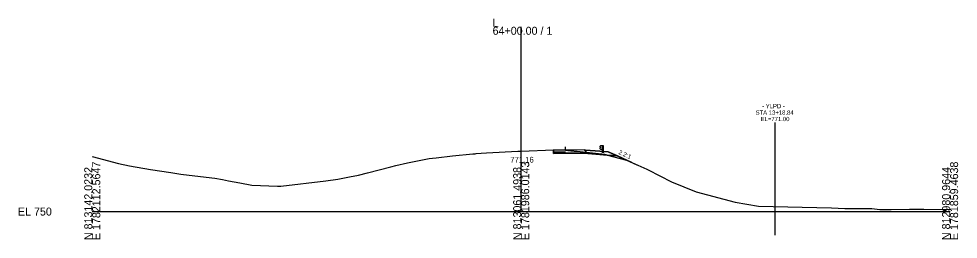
# Model space of a CAD drawing. Extents: x -26 to 7903, y -10 to 9573.
# Drawn here: x 2974.3 to 3302.8, y 4990.3 to 5067.5 of the extents above; entities that cross this region are included whole.
import ezdxf

# ---------------------------------------------------------------- set-up
doc = ezdxf.new("R2010")
doc.units = 0
for name, color, linetype in [('Exist Cross Section Cell', 7, 'Continuous'), ('Exist XS Center Line Elevation Label', 7, 'Continuous'), ('Exist XS Ground Line', 7, 'Continuous'), ('Prop XS Dump Level', 7, 'Continuous'), ('Prop XS Earthwork Shape', 7, 'Continuous'), ('Prop XS EOT Tick Mark', 7, 'Continuous'), ('Prop XS Finish Grade', 7, 'Continuous'), ('Prop XS Finish Grade Earthwork', 7, 'Continuous'), ('Prop XS Finish Grade Paved Shoulder', 7, 'Continuous'), ('Prop XS Finish Grade Pavement', 7, 'Continuous'), ('Prop XS Guardrail', 7, 'Continuous'), ('Prop XS Hydro Fill Slope Data', 7, 'Continuous'), ('Prop XS Pvmt Edge Slope', 7, 'Continuous'), ('Prop XS Side Slope Text', 7, 'Continuous'), ('Prop XS Subgrade Earthwork', 7, 'Continuous'), ('Prop XS Vertical Lines Alignments', 7, 'Continuous'), ('Scratch_Level_3', 7, 'Continuous'), ('Scratch_Level_6', 7, 'Continuous')]:
    doc.layers.add(name, color=color, linetype=linetype)

msp = doc.modelspace()

# ---------------------------------------------------------------- linework, layer by layer
at = {"layer": 'Exist Cross Section Cell'}
for p, q in [((3150, 5000), (3150, 5064.71)), ((3000, 5000), (3150, 5000)), ((3150, 5000), (3300, 5000))]:
    msp.add_line(p, q, dxfattribs=at)
at = {"layer": 'Exist XS Ground Line'}
for p, q in [((3125.93, 5019.46), (3133.12, 5020.18)), ((3133.12, 5020.18), (3133.86, 5020.26)), ((3133.86, 5020.26), (3134.21, 5020.29)), ((3134.21, 5020.29), (3135.97, 5020.4)), ((3135.97, 5020.4), (3137.93, 5020.52)), ((3137.93, 5020.52), (3148.78, 5021.12)), ((3148.78, 5021.12), (3150, 5021.16)), ((3150, 5021.16), (3161.29, 5021.57)), ((3161.29, 5021.57), (3165.46, 5021.52)), ((3165.46, 5021.52), (3166.29, 5021.43)), ((3166.29, 5021.43), (3179.23, 5019.93)), ((3000, 5019.3), (3009.18, 5016.79)), ((3009.18, 5016.79), (3012.99, 5016.06)), ((3106.16, 5016.1), (3110.22, 5017.11)), ((3110.22, 5017.11), (3117.79, 5018.53)), ((3117.79, 5018.53), (3118.95, 5018.75)), ((3118.95, 5018.75), (3120.22, 5018.87)), ((3120.22, 5018.87), (3125.93, 5019.46)), ((3179.23, 5019.93), (3179.67, 5019.89)), ((3179.67, 5019.89), (3180.16, 5019.75)), ((3180.16, 5019.75), (3186.86, 5017.94)), ((3186.86, 5017.94), (3187.23, 5017.83)), ((3187.23, 5017.83), (3188.65, 5017.23)), ((3188.65, 5017.23), (3193.98, 5014.82)), ((3012.99, 5016.06), (3020.36, 5014.73)), ((3020.36, 5014.73), (3027.43, 5013.63)), ((3027.43, 5013.63), (3030.96, 5013.1)), ((3093.08, 5012.79), (3096.27, 5013.61)), ((3096.27, 5013.61), (3104.37, 5015.7)), ((3104.37, 5015.7), (3106.16, 5016.1)), ((3193.98, 5014.82), (3194.44, 5014.58)), ((3194.44, 5014.58), (3202.6, 5010.44)), ((3030.96, 5013.1), (3039.83, 5012)), ((3039.83, 5012), (3042.84, 5011.66)), ((3042.84, 5011.66), (3045.5, 5011.2)), ((3045.5, 5011.2), (3047.69, 5010.74)), ((3047.69, 5010.74), (3051.58, 5010.03)), ((3065.92, 5008.86), (3081.69, 5010.7)), ((3081.69, 5010.7), (3085.9, 5011.36)), ((3085.9, 5011.36), (3090, 5012.18)), ((3090, 5012.18), (3093.08, 5012.79)), ((3202.6, 5010.44), (3211.15, 5006.95)), ((3051.58, 5010.03), (3055.79, 5009.23)), ((3055.79, 5009.23), (3064.77, 5008.94)), ((3064.77, 5008.94), (3065.92, 5008.86)), ((3211.15, 5006.95), (3224.84, 5003.31)), ((3224.84, 5003.31), (3233.05, 5001.88)), ((3233.05, 5001.88), (3258.55, 5001.26)), ((3258.55, 5001.26), (3263.17, 5001.05)), ((3263.17, 5001.05), (3272.63, 5001.06)), ((3272.63, 5001.06), (3275.44, 5000.75)), ((3275.44, 5000.75), (3279.41, 5000.76)), ((3279.41, 5000.76), (3285.85, 5000.83)), ((3285.85, 5000.83), (3286.83, 5000.87)), ((3286.83, 5000.87), (3288.42, 5000.86)), ((3288.42, 5000.86), (3290.78, 5000.83)), ((3290.78, 5000.83), (3300, 5000.69))]:
    msp.add_line(p, q, dxfattribs=at)
at = {"layer": 'Prop XS Dump Level'}
for p, q in [((3161.24, 5020.94), (3165.47, 5020.85)), ((3165.47, 5020.85), (3161.24, 5020.94))]:
    msp.add_line(p, q, dxfattribs=at)
at = {"layer": 'Prop XS Earthwork Shape'}
for points in [[(3161.3, 5020.32), (3165.47, 5020.47), (3169.47, 5020.39), (3173.29, 5020.31), (3177.47, 5019.98), (3180.12, 5019.77), (3179.67, 5019.89), (3179.23, 5019.93), (3166.29, 5021.43), (3165.46, 5021.52), (3161.3, 5021.57)], [(3180.12, 5019.77), (3180.16, 5019.75), (3186.86, 5017.94), (3187.23, 5017.83), (3188.65, 5017.23), (3183.64, 5019.48)]]:
    msp.add_lwpolyline(points, close=True, dxfattribs=at)
at = {"layer": 'Prop XS EOT Tick Mark'}
msp.add_line((3165.47, 5021.72), (3165.47, 5022.72), dxfattribs=at)
at = {"layer": 'Prop XS Finish Grade'}
for p, q in [((3172.02, 5021.59), (3172.47, 5021.55)), ((3172.47, 5021.55), (3177.47, 5021.15)), ((3177.47, 5021.15), (3180.47, 5020.91)), ((3180.47, 5020.91), (3183.64, 5019.48))]:
    msp.add_line(p, q, dxfattribs=at)
at = {"layer": 'Prop XS Finish Grade Earthwork'}
msp.add_line((3183.64, 5019.48), (3190.49, 5016.39), dxfattribs=at)
at = {"layer": 'Prop XS Finish Grade Paved Shoulder'}
msp.add_line((3165.47, 5021.72), (3172.02, 5021.59), dxfattribs=at)
at = {"layer": 'Prop XS Finish Grade Pavement'}
msp.add_line((3161.3, 5021.57), (3165.47, 5021.72), dxfattribs=at)
at = {"layer": 'Prop XS Guardrail'}
for p, q in [((3177.5, 5022.82), (3177.47, 5022.76)), ((3177.47, 5022.76), (3177.5, 5022.7)), ((3177.5, 5022.21), (3177.47, 5022.15)), ((3177.47, 5022.15), (3177.5, 5022.09)), ((3177.79, 5023.02), (3177.5, 5022.82)), ((3177.5, 5022.7), (3177.79, 5022.5)), ((3177.79, 5022.41), (3177.5, 5022.21)), ((3177.5, 5022.09), (3177.79, 5021.89)), ((3178.29, 5023.02), (3177.79, 5023.02)), ((3177.79, 5022.5), (3177.79, 5022.41)), ((3177.79, 5021.89), (3178.29, 5021.89)), ((3178.79, 5023.02), (3178.29, 5023.02)), ((3178.29, 5023.02), (3178.29, 5020.52)), ((3178.79, 5020.52), (3178.79, 5023.02))]:
    msp.add_line(p, q, dxfattribs=at)
at = {"layer": 'Prop XS Hydro Fill Slope Data'}
msp.add_line((3180.47, 5020.91), (3190.49, 5016.39), dxfattribs=at)
at = {"layer": 'Prop XS Pvmt Edge Slope'}
msp.add_line((3172.02, 5021.59), (3173.29, 5020.31), dxfattribs=at)
at = {"layer": 'Prop XS Subgrade Earthwork'}
for p, q in [((3161.3, 5020.32), (3161.3, 5021.57)), ((3161.3, 5020.32), (3165.47, 5020.47)), ((3165.47, 5020.47), (3169.47, 5020.39)), ((3169.47, 5020.39), (3173.29, 5020.31)), ((3173.29, 5020.31), (3177.47, 5019.98)), ((3177.47, 5019.98), (3183.64, 5019.48))]:
    msp.add_line(p, q, dxfattribs=at)
at = {"layer": 'Prop XS Vertical Lines Alignments'}
msp.add_line((3238.76, 5031.16), (3238.76, 4991.74), dxfattribs=at)
at = {"layer": 'Scratch_Level_3'}
for p, q in [((3172.47, 5021.55), (3172.02, 5021.59)), ((3172.02, 5021.59), (3173.29, 5020.31)), ((3177.47, 5021.15), (3172.47, 5021.55)), ((3173.29, 5020.31), (3177.47, 5019.98)), ((3180.47, 5020.91), (3177.47, 5021.15)), ((3183.64, 5019.48), (3180.47, 5020.91)), ((3177.47, 5019.98), (3183.64, 5019.48))]:
    msp.add_line(p, q, dxfattribs=at)
at = {"layer": 'Scratch_Level_6'}
msp.add_lwpolyline([(3179.67, 5019.89), (3180.12, 5019.77), (3177.47, 5019.98), (3173.29, 5020.31), (3169.47, 5020.39), (3165.47, 5020.47), (3161.3, 5020.32), (3161.3, 5021.57), (3165.46, 5021.52), (3166.29, 5021.43), (3179.23, 5019.93)], close=True, dxfattribs=at)

# ---------------------------------------------------------------- texts
at = {"layer": 'Exist Cross Section Cell'}
for s, p in [('L', (3140, 5064.71)), ('64+00.00 / 1', (3140, 5061.91)), ('EL 750', (2974, 4998.6))]:
    msp.add_text(s, height=2.8, dxfattribs=at).set_placement(p)
for s, p in [('E 1782112.5647', (3002.8, 4990)), ('E 1781986.0143', (3152.8, 4990)), ('E 1781859.4638', (3302.8, 4990)), ('N 813142.0232', (3000, 4990)), ('N 813061.4938', (3150, 4990)), ('N 812980.9644', (3300, 4990))]:
    msp.add_text(s, height=2.8, rotation=90, dxfattribs=at).set_placement(p)
at = {"layer": 'Exist XS Center Line Elevation Label'}
msp.add_text('771.16', height=2, dxfattribs=at).set_placement((3146.21, 5017.16))
at = {"layer": 'Prop XS Dump Level'}
for s, height, p in [('Eop', 0.3, (3161.3, 5021.27)), ('Case4', 0.04, (3177.47, 5020.96))]:
    msp.add_text(s, height=height, dxfattribs=at).set_placement(p)
at = {"layer": 'Prop XS Side Slope Text'}
msp.add_text('2.2:1', height=1.5, rotation=335.5181, dxfattribs=at).set_placement((3183.89, 5020.23))
at = {"layer": 'Prop XS Vertical Lines Alignments'}
for s, p in [('- YLPD -', (3234.27, 5036.16)), ('STA 13+18.84', (3231.99, 5033.91)), ('EL=771.00', (3233.75, 5031.66))]:
    msp.add_text(s, height=1.5, dxfattribs=at).set_placement(p)

doc.saveas('drawing.dxf')
